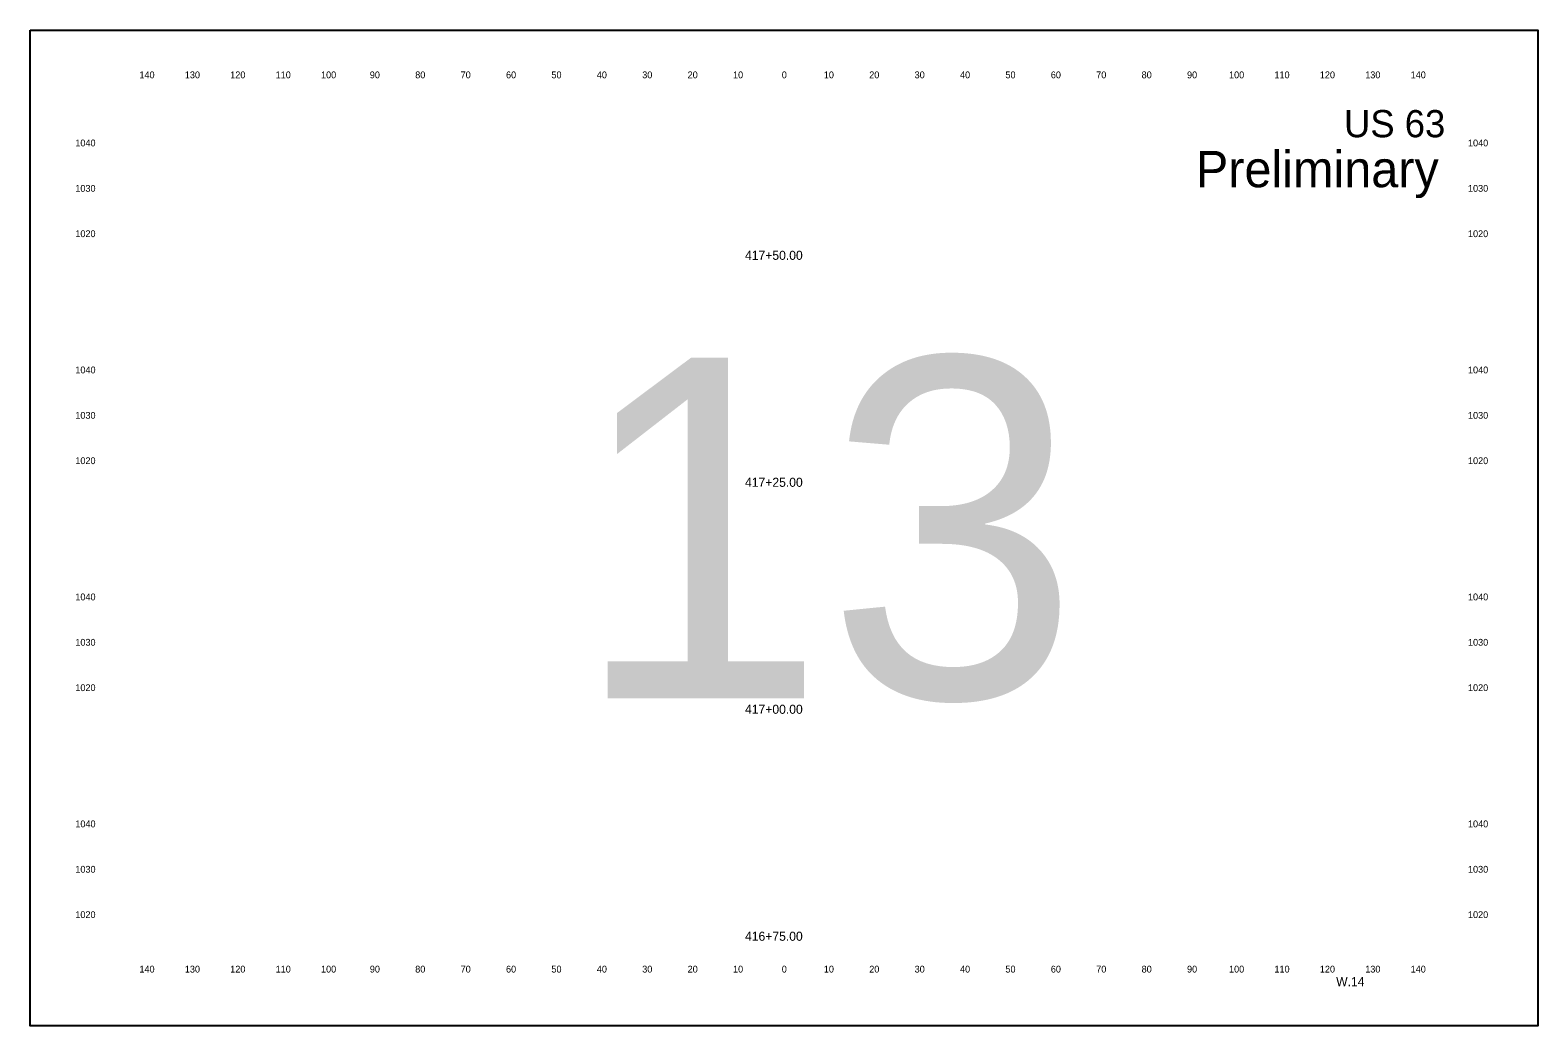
# Model space of a CAD drawing. Extents: x 10123 to 17295, y 9730 to 10181.
# Drawn here: x 14443.2 to 14775.3, y 9730.3 to 9949.6 of the extents above; entities that cross this region are included whole.
import ezdxf

# ---------------------------------------------------------------- set-up
doc = ezdxf.new("R2010")
doc.units = 0
for name, color, linetype in [('dsnTextCpn', 7, 'Continuous'), ('dsnTextCpnTitleSheetLocDesc', 7, 'Continuous'), ('dsnTextCpnTitleSheetPIN', 7, 'Continuous'), ('dsnTextCpnTitleSheetWorkType', 7, 'Continuous')]:
    doc.layers.add(name, color=color, linetype=linetype)

msp = doc.modelspace()

# ---------------------------------------------------------------- linework, layer by layer
at = {"layer": 'dsnTextCpnTitleSheetWorkType'}
msp.add_lwpolyline([(14443.21, 9949.6), (14775.29, 9949.6), (14775.29, 9730.26), (14443.21, 9730.26)], close=True, dxfattribs=at)

# ---------------------------------------------------------------- texts
at = {"layer": 'dsnTextCpn'}
for s, height, p in [('140', 1.5, (14467.27, 9939)), ('130', 1.5, (14477.27, 9939)), ('120', 1.5, (14487.27, 9939)), ('110', 1.5, (14497.27, 9939)), ('100', 1.5, (14507.27, 9939)), ('90', 1.5, (14518.02, 9939)), ('80', 1.5, (14528.02, 9939)), ('70', 1.5, (14538.02, 9939)), ('60', 1.5, (14548.02, 9939)), ('50', 1.5, (14558.02, 9939)), ('40', 1.5, (14568.02, 9939)), ('30', 1.5, (14578.02, 9939)), ('20', 1.5, (14588.02, 9939)), ('10', 1.5, (14598.02, 9939)), ('0', 1.5, (14608.76, 9939)), ('0', 1.5, (14608.76, 9939)), ('10', 1.5, (14618.02, 9939)), ('20', 1.5, (14628.02, 9939)), ('30', 1.5, (14638.02, 9939)), ('40', 1.5, (14648.02, 9939)), ('50', 1.5, (14658.02, 9939)), ('60', 1.5, (14668.02, 9939)), ('70', 1.5, (14678.02, 9939)), ('80', 1.5, (14688.02, 9939)), ('90', 1.5, (14698.02, 9939)), ('100', 1.5, (14707.27, 9939)), ('110', 1.5, (14717.27, 9939)), ('120', 1.5, (14727.27, 9939)), ('130', 1.5, (14737.27, 9939)), ('140', 1.5, (14747.27, 9939)), ('US 63', 6, (14732.6, 9926)), ('1040', 1.5, (14453.15, 9924)), ('1040', 1.5, (14759.9, 9924)), ('1030', 1.5, (14453.15, 9914)), ('1030', 1.5, (14759.9, 9914)), ('1020', 1.5, (14453.15, 9904)), ('1020', 1.5, (14759.9, 9904)), ('417+50.00', 2, (14600.66, 9899)), ('1040', 1.5, (14453.15, 9874)), ('1040', 1.5, (14759.9, 9874)), ('1030', 1.5, (14453.15, 9864)), ('1030', 1.5, (14759.9, 9864)), ('1020', 1.5, (14453.15, 9854)), ('1020', 1.5, (14759.9, 9854)), ('417+25.00', 2, (14600.66, 9849)), ('1040', 1.5, (14453.15, 9824)), ('1040', 1.5, (14759.9, 9824)), ('1030', 1.5, (14453.15, 9814)), ('1030', 1.5, (14759.9, 9814)), ('1020', 1.5, (14453.15, 9804)), ('1020', 1.5, (14759.9, 9804)), ('417+00.00', 2, (14600.66, 9799)), ('1040', 1.5, (14453.15, 9774)), ('1040', 1.5, (14759.9, 9774)), ('1030', 1.5, (14453.15, 9764)), ('1030', 1.5, (14759.9, 9764)), ('1020', 1.5, (14453.15, 9754)), ('1020', 1.5, (14759.9, 9754)), ('416+75.00', 2, (14600.66, 9749)), ('140', 1.5, (14467.27, 9742)), ('130', 1.5, (14477.27, 9742)), ('120', 1.5, (14487.27, 9742)), ('110', 1.5, (14497.27, 9742)), ('100', 1.5, (14507.27, 9742)), ('90', 1.5, (14518.02, 9742)), ('80', 1.5, (14528.02, 9742)), ('70', 1.5, (14538.02, 9742)), ('60', 1.5, (14548.02, 9742)), ('50', 1.5, (14558.02, 9742)), ('40', 1.5, (14568.02, 9742)), ('30', 1.5, (14578.02, 9742)), ('20', 1.5, (14588.02, 9742)), ('10', 1.5, (14598.02, 9742)), ('0', 1.5, (14608.76, 9742)), ('0', 1.5, (14608.76, 9742)), ('10', 1.5, (14618.02, 9742)), ('20', 1.5, (14628.02, 9742)), ('30', 1.5, (14638.02, 9742)), ('40', 1.5, (14648.02, 9742)), ('50', 1.5, (14658.02, 9742)), ('60', 1.5, (14668.02, 9742)), ('70', 1.5, (14678.02, 9742)), ('80', 1.5, (14688.02, 9742)), ('90', 1.5, (14698.02, 9742)), ('100', 1.5, (14707.27, 9742)), ('110', 1.5, (14717.27, 9742)), ('120', 1.5, (14727.27, 9742)), ('130', 1.5, (14737.27, 9742)), ('140', 1.5, (14747.27, 9742))]:
    msp.add_text(s, height=height, dxfattribs=at).set_placement(p)
at = {"layer": 'dsnTextCpnTitleSheetLocDesc'}
msp.add_text('Preliminary', height=8, dxfattribs=at).set_placement((14699.97, 9915))
at = {"layer": 'dsnTextCpnTitleSheetPIN'}
msp.add_text('W.14', height=2, dxfattribs=at).set_placement((14730.87, 9739))
at = {"layer": 'dsnTextCpnTitleSheetWorkType'}
msp.add_text('13', height=75, dxfattribs=at).set_placement((14562.8, 9802.43))

doc.saveas('drawing.dxf')
